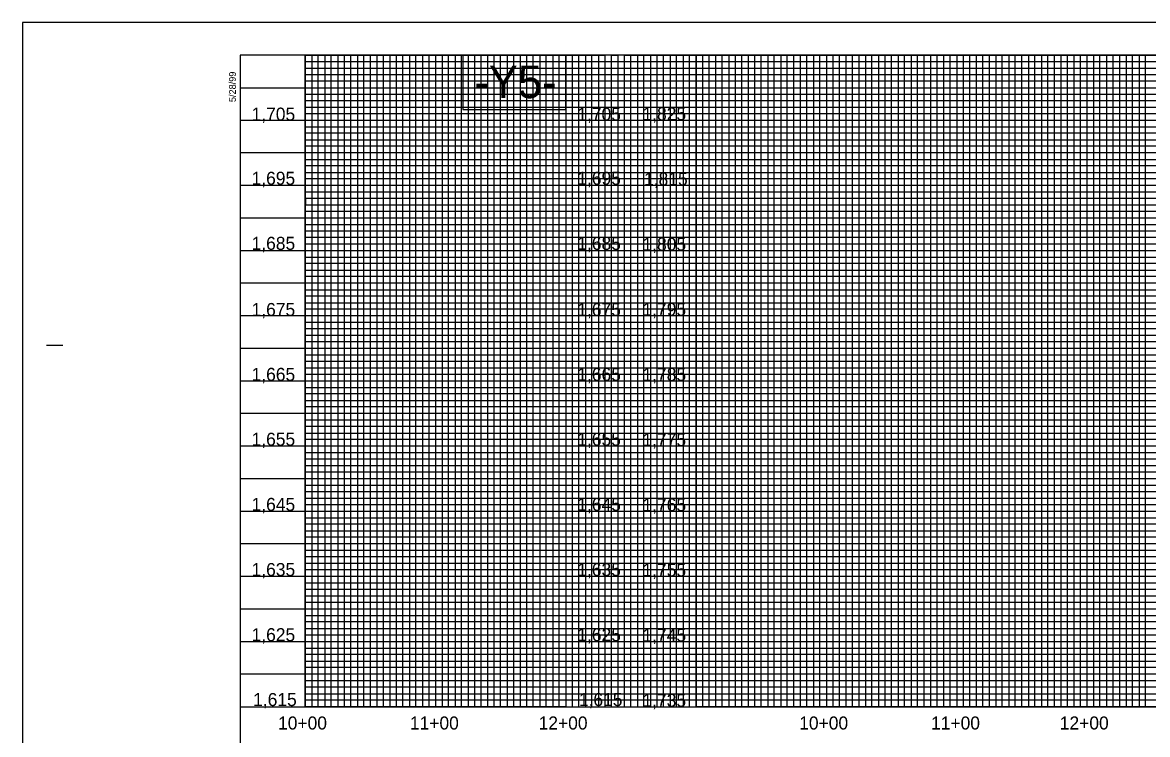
# Model space of a CAD drawing. Extents: x 505602 to 507286, y 483109 to 489436.
# Drawn here: x 505602 to 506466, y 483662 to 484209 of the extents above; entities that cross this region are included whole.
import ezdxf

# ---------------------------------------------------------------- set-up
doc = ezdxf.new("R2010")
doc.units = 0
for name, color, linetype in [('Exist Vertical Profile Vertical Axis Label', 7, 'Continuous'), ('Old_Level_1', 7, 'Continuous'), ('Prop Grid Mask', 7, 'Continuous'), ('Sheet Layout Profile Border Port 1', 7, 'Continuous'), ('Sheet Plot Border Outside CELL', 7, 'Continuous'), ('Sheet Profile CELL', 7, 'Continuous'), ('Sheet Profile Grid Major CELL', 7, 'Continuous'), ('Sheet Profile Grid Middle CELL', 7, 'Continuous'), ('Sheet Profile Grid Minor CELL', 7, 'Continuous')]:
    doc.layers.add(name, color=color, linetype=linetype)

msp = doc.modelspace()

# ---------------------------------------------------------------- linework, layer by layer
at = {"layer": 'Prop Grid Mask'}
msp.add_lwpolyline([(506019.08, 484183.71), (505940.09, 484183.71), (505940.09, 484142), (506019.08, 484142)], close=True, dxfattribs=at)
at = {"layer": 'Sheet Layout Profile Border Port 1'}
for points in [[(505819.08, 484183.71), (506019.08, 484183.71), (506019.08, 483683.71), (505819.08, 483683.71)], [(506119.08, 484183.71), (507069.08, 484183.71), (507069.08, 483683.71), (506119.08, 483683.71)]]:
    msp.add_lwpolyline(points, close=True, dxfattribs=at)
at = {"layer": 'Sheet Plot Border Outside CELL'}
msp.add_lwpolyline([(505602.08, 483108.71), (507286.08, 483108.71), (507286.08, 484208.71), (505602.08, 484208.71)], close=True, dxfattribs=at)
at = {"layer": 'Sheet Profile CELL'}
for p, q in [((506069.08, 483683.71), (506069.08, 484183.71)), ((505620.58, 483961.21), (505633.08, 483961.21)), ((505769.08, 483683.71), (507269.08, 483683.71))]:
    msp.add_line(p, q, dxfattribs=at)
msp.add_lwpolyline([(507269.08, 484183.71), (505769.08, 484183.71), (505769.08, 483133.71), (507269.08, 483133.71)], close=True, dxfattribs=at)
at = {"layer": 'Sheet Profile Grid Major CELL'}
for points in [[(505819.08, 484183.71), (505819.08, 483683.71), (505869.08, 483683.71), (505869.08, 484183.71), (505919.08, 484183.71), (505919.08, 483683.71), (505969.08, 483683.71), (505969.08, 484183.71), (506019.08, 484183.71), (506019.08, 483683.71), (506069.08, 483683.71), (506069.08, 484183.71), (506119.08, 484183.71), (506119.08, 483683.71), (506169.08, 483683.71), (506169.08, 484183.71), (506219.08, 484183.71), (506219.08, 483683.71), (506269.08, 483683.71), (506269.08, 484183.71), (506319.08, 484183.71), (506319.08, 483683.71), (506369.08, 483683.71), (506369.08, 484183.71), (506419.08, 484183.71), (506419.08, 483683.71), (506469.08, 483683.71)], [(505769.08, 484133.71), (507069.08, 484133.71)], [(507069.08, 484083.71), (505769.08, 484083.71), (505769.08, 484033.71), (507069.08, 484033.71)], [(507269.08, 483983.71), (505769.08, 483983.71), (505769.08, 483933.71), (507269.08, 483933.71)], [(507269.08, 483883.71), (505769.08, 483883.71), (505769.08, 483833.71), (507269.08, 483833.71)], [(507269.08, 483783.71), (505769.08, 483783.71), (505769.08, 483783.71), (505769.08, 483733.71), (507269.08, 483733.71)]]:
    msp.add_lwpolyline(points, dxfattribs=at)
at = {"layer": 'Sheet Profile Grid Middle CELL'}
msp.add_line((505769.08, 484158.71), (507069.03, 484158.71), dxfattribs=at)
msp.add_line((505769.08, 484158.71), (507069.03, 484158.71), dxfattribs=at)
for points in [[(505844.08, 484183.71), (505844.08, 483683.71), (505894.08, 483683.71), (505894.08, 484183.71), (505944.08, 484183.71), (505944.08, 483683.71), (505994.08, 483683.71), (505994.08, 484183.71), (506044.08, 484183.71), (506044.08, 483683.71), (506094.08, 483683.71), (506094.08, 484183.71), (506144.08, 484183.71), (506144.08, 483683.71), (506194.08, 483683.71), (506194.08, 484183.71), (506244.08, 484183.71), (506244.08, 483683.71), (506294.08, 483683.71), (506294.08, 484183.71), (506344.08, 484183.71), (506344.08, 483683.71), (506394.08, 483683.71), (506394.08, 483683.71), (506394.08, 484183.71), (506444.08, 484183.71), (506444.08, 483683.71), (506494.08, 483683.71)], [(507069.08, 484108.71), (505769.08, 484108.71), (505769.08, 484058.71), (507069.08, 484058.71)], [(507269.08, 484008.71), (505769.08, 484008.71), (505769.08, 483958.71), (507094.08, 483958.71)], [(507269.08, 483908.71), (505769.08, 483908.71), (505769.08, 483858.71), (507269.08, 483858.71)], [(507269.08, 483808.71), (505769.08, 483808.71), (505769.08, 483758.71), (507269.08, 483758.71)], [(507269.08, 483708.71), (505769.08, 483708.71)]]:
    msp.add_lwpolyline(points, dxfattribs=at)
at = {"layer": 'Sheet Profile Grid Minor CELL'}
for p, q in [((505819.08, 484178.71), (507069.08, 484178.71)), ((505819.08, 484173.71), (505819.08, 484173.71)), ((507069.08, 484173.71), (505819.08, 484173.36)), ((505819.08, 484168.71), (507069.08, 484168.71)), ((507069.03, 484048.71), (505819.08, 484048.71)), ((507069.08, 484043.71), (505819.08, 484043.71)), ((507069.08, 484038.71), (505819.08, 484038.71)), ((505819.08, 484028.71), (507069.08, 484028.71)), ((507069.08, 484023.71), (505819.08, 484023.71)), ((505819.08, 484018.71), (507219.08, 484018.71)), ((507219.08, 483998.71), (505819.08, 483998.71)), ((505819.08, 483993.71), (507219.08, 483993.71)), ((507219.08, 483973.71), (505819.08, 483973.71)), ((505819.08, 483968.71), (507219.08, 483968.71)), ((507219.08, 483948.71), (505819.08, 483948.71)), ((505819.08, 483943.71), (507219.08, 483943.71)), ((507219.08, 483938.71), (505819.08, 483938.71)), ((505819.08, 483928.71), (507219.08, 483928.71)), ((507219.08, 483923.71), (505819.08, 483923.71)), ((505819.08, 483918.71), (507219.08, 483918.71)), ((507219.08, 483913.71), (505819.08, 483913.71)), ((505819.08, 483903.71), (507219.08, 483903.71)), ((507219.08, 483898.71), (505819.08, 483898.71)), ((505819.08, 483893.71), (507219.08, 483893.71)), ((507219.08, 483888.71), (505819.08, 483888.71)), ((505819.08, 483878.71), (507219.08, 483878.71)), ((507219.08, 483873.71), (505819.08, 483873.71)), ((505819.08, 483868.71), (507219.08, 483868.71)), ((507219.08, 483863.71), (505819.08, 483863.71)), ((505819.08, 483853.71), (507219.08, 483853.71)), ((507219.08, 483848.71), (505819.08, 483848.71)), ((505819.08, 483843.71), (507219.08, 483843.71)), ((507219.08, 483838.71), (505819.08, 483838.71)), ((505819.08, 483828.71), (507219.08, 483828.71)), ((507219.08, 483823.71), (505819.08, 483823.71)), ((505819.08, 483818.71), (507219.08, 483818.71)), ((507219.08, 483813.71), (505819.08, 483813.71)), ((505819.08, 483803.71), (507219.08, 483803.71)), ((507219.08, 483798.71), (505819.08, 483798.71)), ((507219.08, 483793.71), (505819.08, 483793.71)), ((507219.08, 483788.71), (505819.08, 483788.71)), ((505819.08, 483778.71), (507219.08, 483778.71)), ((507219.08, 483773.71), (505819.08, 483773.71)), ((505819.08, 483768.71), (507219.08, 483768.71)), ((507219.08, 483763.71), (505819.08, 483763.71)), ((505819.08, 483753.71), (507219.08, 483753.71)), ((507219.08, 483748.71), (505819.08, 483748.71)), ((505819.08, 483743.71), (507219.08, 483743.71)), ((507219.08, 483738.71), (505819.08, 483738.71)), ((505819.08, 483728.71), (507219.08, 483728.71)), ((507219.08, 483723.71), (505819.08, 483723.71)), ((505819.08, 483718.71), (507219.08, 483718.71)), ((507219.08, 483713.71), (505819.08, 483713.71)), ((505819.08, 483703.71), (507219.08, 483703.71)), ((507219.08, 483698.71), (505819.08, 483698.71)), ((505819.08, 483693.71), (507219.08, 483693.71))]:
    msp.add_line(p, q, dxfattribs=at)
for points in [[(505824.08, 484183.71), (505824.08, 483683.71), (505829.08, 483683.71), (505829.08, 484183.71), (505834.08, 484183.71), (505834.08, 483683.71), (505839.08, 483683.71), (505839.08, 484183.71), (505849.08, 484183.71), (505849.08, 483683.71), (505854.08, 483683.71), (505854.08, 484183.71), (505859.08, 484183.71), (505859.08, 483683.71), (505864.08, 483683.71), (505874.08, 483683.71), (505879.08, 483683.71), (505879.08, 484183.71), (505884.08, 484183.71), (505884.08, 483683.71), (505889.08, 483683.71), (505889.08, 484183.71), (505899.08, 484183.71), (505899.08, 483683.71), (505904.08, 483683.71), (505904.08, 484183.71), (505909.08, 484183.71), (505909.08, 483683.71), (505914.08, 483683.71), (505914.08, 484183.71), (505924.08, 484183.71), (505924.08, 483683.71), (505929.08, 483683.71), (505929.08, 484183.71), (505934.08, 484183.71), (505934.08, 483683.71), (505939.08, 483683.71), (505939.08, 484183.71), (505949.08, 484183.71), (505949.08, 483683.71), (505954.08, 483683.71), (505954.08, 484183.71), (505959.08, 484183.71), (505959.08, 483683.71), (505964.08, 483683.71), (505964.08, 484183.71), (505974.08, 484183.71), (505974.08, 483683.71), (505979.08, 483683.71), (505979.08, 484183.71), (505984.08, 484183.71), (505984.08, 483683.71), (505989.08, 483683.71), (505989.08, 484183.71), (505999.08, 484183.71), (505999.08, 483683.71), (506004.08, 483683.71), (506004.08, 484183.71), (506009.08, 484183.71), (506009.08, 483683.71), (506014.08, 483683.71), (506014.08, 484183.71), (506024.08, 484183.71), (506024.08, 483683.71), (506029.08, 483683.71), (506029.08, 484183.71), (506034.08, 484183.71), (506034.08, 483683.71)], [(505864.08, 483683.71), (505864.08, 484183.71), (505874.08, 484183.71), (505874.08, 483683.71)], [(506034.08, 483683.71), (506039.08, 483683.71), (506039.08, 484183.71), (506049.08, 484183.71), (506049.08, 483683.71), (506054.08, 483683.71), (506054.08, 484183.71), (506059.08, 484183.71), (506059.08, 483683.71), (506064.08, 483683.71), (506064.08, 484183.71), (506074.08, 484183.71), (506074.08, 483683.71), (506079.08, 483683.71), (506079.08, 484183.71), (506084.08, 484183.71), (506084.08, 483683.71), (506089.08, 483683.71), (506089.08, 484183.71), (506099.08, 484183.71), (506099.08, 483683.71), (506104.08, 483683.71), (506104.08, 484183.71), (506109.08, 484183.71), (506109.08, 483683.71), (506114.08, 483683.71), (506114.08, 484183.71), (506124.08, 484183.71), (506124.08, 483683.71), (506129.08, 483683.71), (506129.08, 484183.71), (506134.08, 484183.71), (506134.08, 483683.71), (506139.08, 483683.71), (506139.08, 484183.71), (506149.08, 484183.71), (506149.08, 483683.71), (506154.08, 483683.71), (506154.08, 484183.71), (506159.08, 484183.71), (506159.08, 483683.71), (506164.08, 483683.71), (506164.08, 484183.71), (506174.08, 484183.71), (506174.08, 483683.71), (506179.08, 483683.71), (506179.08, 484183.71), (506184.08, 484183.71), (506184.08, 483683.71), (506189.08, 483683.71), (506189.08, 484183.71), (506199.08, 484183.71), (506199.08, 483683.71), (506204.08, 483683.71), (506204.08, 484183.71), (506209.08, 484183.71), (506209.08, 483683.71), (506214.08, 483683.71), (506214.08, 484183.71), (506224.08, 484183.71), (506224.08, 483683.71), (506229.08, 483683.71), (506229.08, 484183.71), (506234.08, 484183.71), (506234.08, 483683.71), (506239.08, 483683.71), (506239.08, 484183.71), (506249.08, 484183.71), (506249.08, 483683.71), (506254.08, 483683.71), (506254.08, 484183.71), (506259.08, 484183.71), (506259.08, 483683.71), (506264.08, 483683.71), (506264.08, 484183.71), (506274.08, 484183.71), (506274.08, 483683.71), (506279.08, 483683.71), (506279.08, 484183.71), (506284.08, 484183.71), (506284.08, 483683.71), (506289.08, 483683.71), (506289.08, 484183.71), (506299.08, 484183.71), (506299.08, 483683.71), (506304.08, 483683.71), (506304.08, 484183.71), (506309.08, 484183.71), (506309.08, 483683.71), (506314.08, 483683.71), (506314.08, 484183.71), (506324.08, 484183.71), (506324.08, 483683.71), (506329.08, 483683.71), (506329.08, 484183.71), (506334.08, 484183.71), (506334.08, 483683.71), (506339.08, 483683.71), (506339.08, 484183.71), (506349.08, 484183.71)], [(506349.08, 484183.71), (506349.08, 483683.71), (506354.08, 483683.71), (506354.08, 484183.71), (506359.08, 484183.71), (506359.08, 483683.71), (506364.08, 483683.71), (506364.08, 484183.71), (506374.08, 484183.71), (506374.08, 483683.71), (506379.08, 483683.71), (506379.08, 484183.71), (506384.08, 484183.71), (506384.08, 483683.71), (506389.08, 483683.71), (506389.08, 484183.71), (506399.08, 484183.71), (506399.08, 483683.71), (506404.08, 483683.71), (506404.08, 484183.71), (506409.08, 484183.71), (506409.08, 483683.71), (506414.08, 483683.71), (506414.08, 484183.71), (506424.08, 484183.71), (506424.08, 483683.71), (506429.08, 483683.71), (506429.08, 484183.71), (506434.08, 484183.71), (506434.08, 483683.71), (506439.08, 483683.71), (506439.08, 484183.71), (506449.08, 484183.71), (506449.08, 483683.71), (506454.08, 483683.71), (506454.08, 484183.71), (506459.08, 484183.71), (506459.08, 483683.71), (506464.08, 483683.71), (506464.08, 484183.71), (506474.08, 484183.71)], [(507069.08, 484163.71), (505819.08, 484163.71), (505819.08, 484153.71), (507069.08, 484153.71)], [(507069.03, 484148.71), (505819.08, 484148.71), (505819.08, 484143.71), (507069.08, 484143.71)], [(507069.08, 484138.71), (505819.08, 484138.71), (505819.08, 484128.71), (507069.08, 484128.71)], [(507069.08, 484123.71), (505819.08, 484123.71), (505819.08, 484118.71), (507069.08, 484118.71)], [(507069.08, 484113.71), (505819.08, 484113.71), (505819.08, 484103.71), (507069.08, 484103.71)], [(507069.08, 484098.71), (505819.08, 484098.71), (505819.08, 484093.71), (507069.08, 484093.71)], [(507069.08, 484088.71), (505819.08, 484088.71), (505819.08, 484078.71), (507069.08, 484078.71)], [(507069.08, 484073.61), (505819.18, 484073.61), (505819.18, 484068.71), (507069.08, 484068.71)], [(507069.08, 484063.71), (505819.08, 484063.71), (505819.08, 484053.71), (507069.08, 484053.71)], [(507219.08, 484013.71), (505819.08, 484013.71), (505819.08, 484003.71), (507219.08, 484003.71)], [(507219.08, 483988.71), (505819.08, 483988.71), (505819.08, 483978.71), (507219.08, 483978.71)], [(507219.08, 483963.71), (505819.08, 483963.71), (505819.08, 483953.71), (507219.08, 483953.71)], [(507219.08, 483688.71), (505819.08, 483688.71)]]:
    msp.add_lwpolyline(points, dxfattribs=at)

# ---------------------------------------------------------------- texts
at = {"layer": 'Exist Vertical Profile Vertical Axis Label'}
for s, p in [('1,705', (505777.9, 484133.4)), ('1,705', (506027.9, 484133.4)), ('1,825', (506077.93, 484133.64)), ('1,695', (505777.9, 484084.19)), ('1,695', (506027.9, 484084.19)), ('1,815', (506079.13, 484083.64)), ('1,685', (505777.9, 484034.26)), ('1,685', (506027.9, 484034.26)), ('1,805', (506077.93, 484033.64)), ('1,675', (505777.9, 483983.48)), ('1,675', (506027.9, 483983.48)), ('1,795', (506077.93, 483983.64)), ('1,665', (505777.9, 483933.72)), ('1,665', (506027.9, 483933.72)), ('1,785', (506077.93, 483933.64)), ('1,655', (505777.9, 483883.96)), ('1,655', (506027.9, 483883.96)), ('1,775', (506077.93, 483883.64)), ('1,645', (505777.9, 483833.96)), ('1,645', (506027.9, 483833.96)), ('1,765', (506077.93, 483833.64)), ('1,635', (505777.9, 483783.96)), ('1,635', (506027.9, 483783.96)), ('1,755', (506077.93, 483783.64)), ('1,625', (505777.9, 483733.96)), ('1,625', (506027.9, 483733.96)), ('1,745', (506077.93, 483733.64)), ('1,615', (505779.1, 483684.2)), ('1,615', (506029.1, 483684.2)), ('1,735', (506077.93, 483683.64)), ('10+00', (505798.21, 483666.21)), ('11+00', (505899.41, 483666.21)), ('12+00', (505998.21, 483666.21)), ('10+00', (506198.21, 483666.21)), ('11+00', (506299.41, 483666.21)), ('12+00', (506398.21, 483666.21))]:
    msp.add_text(s, height=10, dxfattribs=at).set_placement(p)
at = {"layer": 'Old_Level_1'}
msp.add_text('-Y5-', height=25, dxfattribs=at).set_placement((505948.82, 484150.68))
at = {"layer": 'Sheet Profile CELL'}
msp.add_text('5/28/99', height=5.25, rotation=90, dxfattribs=at).set_placement((505765.84, 484147.62))

doc.saveas('drawing.dxf')
